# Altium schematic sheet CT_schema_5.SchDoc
size 274 x 160 mm
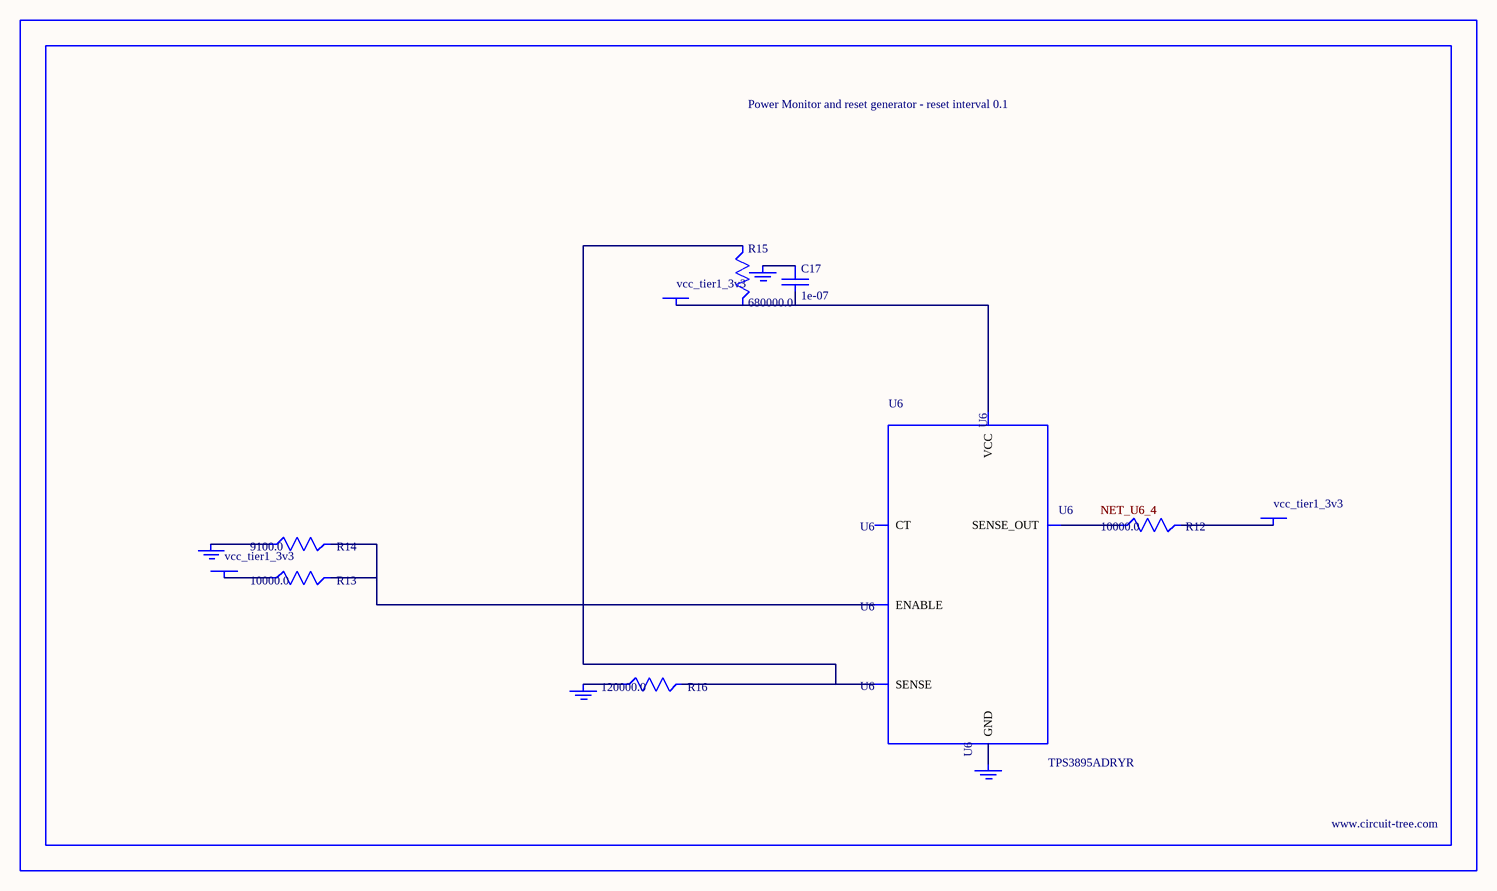
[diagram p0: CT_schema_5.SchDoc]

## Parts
BORDER4  (no value)
C17  1e-07  [C0402]
GND_INSTANCE_4_0  (no value)
GND_INSTANCE_4_1  (no value)
GND_INSTANCE_4_2  (no value)
GND_INSTANCE_4_3  (no value)
POWER_INSTANCE_4_0  vcc_tier1_3v3
POWER_INSTANCE_4_1  vcc_tier1_3v3
POWER_INSTANCE_4_2  vcc_tier1_3v3
R12  10000.0  [R0603]
R13  10000.0  [R0603]
R14  9100.0  [R0603]
R15  680000.0  [R0603]
R16  120000.0  [R0603]
U6  TPS3895ADRYR  [SON-6]

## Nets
NetC17_1: C17.1 GND_INSTANCE_4_2.0(GND)
NetC17_2: C17.2 POWER_INSTANCE_4_2.0(PWR) R15.2 U6.6(VCC)
NetGND_INSTANCE_4_0_0: GND_INSTANCE_4_0.0(GND) R14.1
NetGND_INSTANCE_4_1_0: GND_INSTANCE_4_1.0(GND) R16.1
NetGND_INSTANCE_4_3_0: GND_INSTANCE_4_3.0(GND) U6.2(GND)
NetPOWER_INSTANCE_4_0_0: POWER_INSTANCE_4_0.0(PWR) R13.1
NetPOWER_INSTANCE_4_1_0: POWER_INSTANCE_4_1.0(PWR) R12.2
NetR12_1: R12.1 U6.4(SENSE_OUT)
NetR13_2: R13.2 R14.2 U6.1(ENABLE)
NetR15_1: R15.1 R16.2 U6.3(SENSE)

Not connected (* = marked no-connect by the designer): U6 5(CT)

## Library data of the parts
BORDER4 = BORDER_PAGE4
C17 = C0402C104K3RACTU
GND_INSTANCE_4_0-GND_INSTANCE_4_3 = GND
POWER_INSTANCE_4_0-POWER_INSTANCE_4_2 = PWR
R12 R13 = RC0603JR-0710KL
R14 = RC0603JR-079K1L
R15 = RC0603JR-07680KL
R16 = RC0603JR-07120KL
